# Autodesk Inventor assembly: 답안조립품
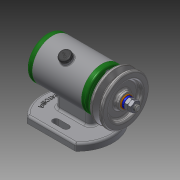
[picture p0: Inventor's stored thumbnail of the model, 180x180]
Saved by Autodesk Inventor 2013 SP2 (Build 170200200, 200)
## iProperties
Created: 2022-02
Part Number: 답안조립품
Document SubType Name: Assembly
Designer: i
Author: i
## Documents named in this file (14)
- C:\Users\i\Desktop\720206V1018\답안조립품.iam
- C:\Users\i\Desktop\720206V1018\본체.ipt
- C:\Users\i\Desktop\720206V1018\V벨트풀리.ipt
- C:\Users\i\Desktop\720206V1018\고무 캡.ipt
- C:\Users\i\Desktop\720206V1018\너트 M8.ipt
- C:\Users\i\Desktop\720206V1018\뒤커버.ipt
- C:\Users\i\Desktop\720206V1018\베어링 6002.ipt
- C:\Users\i\Desktop\720206V1018\볼트 M4 x 10.ipt
- C:\Users\i\Desktop\720206V1018\스프링와셔 8.ipt
- C:\Users\i\Desktop\720206V1018\앞커버.ipt
- C:\Users\i\Desktop\720206V1018\오일 실 15 x 25 x 7.ipt
- C:\Users\i\Desktop\720206V1018\축.ipt
- C:\Users\i\Desktop\720206V1018\키 3 x 3 x 12.ipt
- C:\Users\i\Desktop\720206V1018\평와셔 8 x 17.ipt
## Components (2 placed, 2 different names)
1. V벨트풀리:1
2. 고무 캡:1
